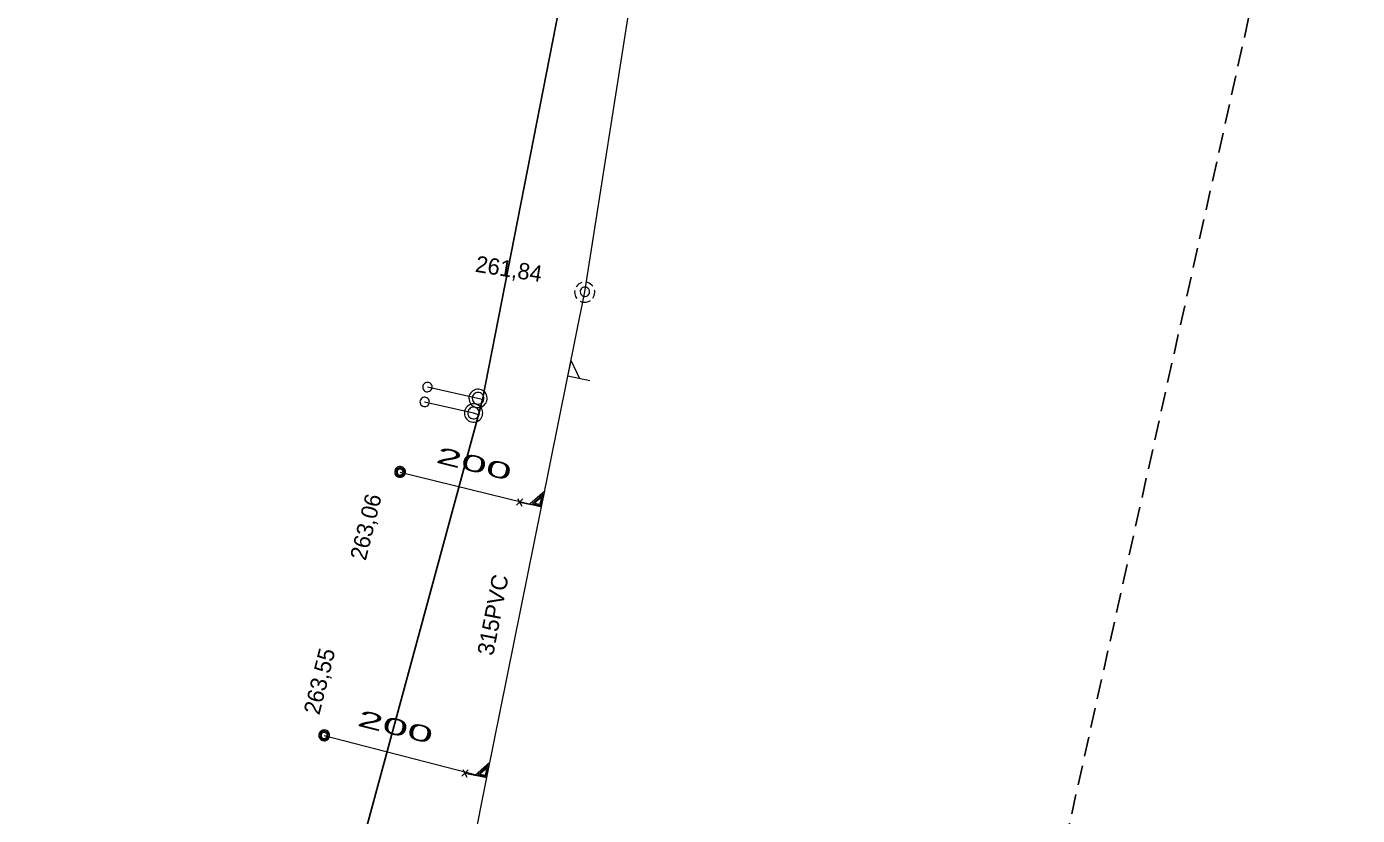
# Model space of a CAD drawing. Extents: x -732096 to -731933, y -1048703 to -1047964.
# Drawn here: x -732033.5 to -731968.4, y -1048192.3 to -1048153.7 of the extents above; entities that cross this region are included whole.
import ezdxf

# ---------------------------------------------------------------- set-up
doc = ezdxf.new("R2010")
doc.units = 0
doc.header["$LTSCALE"] = 0.32
doc.linetypes.add('MEDIUM_DASHED', pattern=[4.5, 3, -1.5])
doc.layers.add('1', color=7, linetype='Continuous')
for name, color, linetype, lineweight in [('18', 7, 'Continuous', 13), ('20', 7, 'Continuous', 13), ('49', 7, 'Continuous', 13), ('63', 7, 'MEDIUM_DASHED', 25), ('8', 7, 'Continuous', 13)]:
    doc.layers.add(name, color=color, linetype=linetype, lineweight=lineweight)

msp = doc.modelspace()

# ---------------------------------------------------------------- linework, layer by layer
at = {"layer": '18'}
for p, q in [((-732009.504, -1048177.097), (-732009.191, -1048176.781)), ((-732009.45, -1048176.762), (-732009.252, -1048177.143)), ((-732012.18, -1048190.343), (-732011.867, -1048190.027)), ((-732012.126, -1048190.008), (-732011.928, -1048190.389))]:
    msp.add_line(p, q, dxfattribs=at)
for points in [[(-732006.313, -1048166.207), (-732006.384, -1048166.235), (-732006.451, -1048166.274), (-732006.511, -1048166.322), (-732006.562, -1048166.379), (-732006.586, -1048166.413)], [(-732005.772, -1048166.39), (-732005.822, -1048166.332), (-732005.88, -1048166.282), (-732005.945, -1048166.241), (-732006.016, -1048166.212), (-732006.065, -1048166.198)], [(-732006.658, -1048166.599), (-732006.664, -1048166.676), (-732006.659, -1048166.753), (-732006.642, -1048166.828), (-732006.613, -1048166.899), (-732006.573, -1048166.965), (-732006.557, -1048166.987)], [(-732005.777, -1048166.976), (-732005.736, -1048166.911), (-732005.705, -1048166.841), (-732005.686, -1048166.766), (-732005.678, -1048166.69), (-732005.683, -1048166.613), (-732005.689, -1048166.578)], [(-732006.4, -1048167.116), (-732006.33, -1048167.147), (-732006.255, -1048167.166), (-732006.179, -1048167.173), (-732006.102, -1048167.168), (-732006.027, -1048167.151), (-732005.955, -1048167.123), (-732005.895, -1048167.088)], [(-732005.918, -1048171.009), (-732006.993, -1048170.792), (-732006.84, -1048170.033), (-732006.428, -1048170.905)], [(-732009.355, -1048176.945), (-732008.281, -1048177.162), (-732008.128, -1048176.406), (-732008.847, -1048177.048)], [(-732008.722, -1048177.021), (-732008.314, -1048177.103), (-732008.202, -1048176.55), (-732008.723, -1048177.021)], [(-732008.63, -1048176.992), (-732008.345, -1048177.049), (-732008.271, -1048176.686), (-732008.63, -1048176.994)], [(-732012.031, -1048190.191), (-732010.957, -1048190.408), (-732010.804, -1048189.652), (-732011.523, -1048190.294)], [(-732011.398, -1048190.267), (-732010.99, -1048190.349), (-732010.878, -1048189.796), (-732011.399, -1048190.267)], [(-732011.306, -1048190.238), (-732011.021, -1048190.295), (-732010.947, -1048189.932), (-732011.306, -1048190.24)]]:
    msp.add_lwpolyline(points, dxfattribs=at)
for points in [[(-732005.929, -1048166.659), (-732005.935, -1048166.607), (-732005.953, -1048166.557), (-732005.981, -1048166.513), (-732006.019, -1048166.476), (-732006.064, -1048166.449), (-732006.114, -1048166.433), (-732006.166, -1048166.428), (-732006.218, -1048166.435), (-732006.267, -1048166.454), (-732006.311, -1048166.484), (-732006.346, -1048166.523), (-732006.372, -1048166.568), (-732006.387, -1048166.619), (-732006.39, -1048166.671), (-732006.382, -1048166.723), (-732006.361, -1048166.771), (-732006.331, -1048166.814), (-732006.291, -1048166.849), (-732006.245, -1048166.873), (-732006.194, -1048166.887), (-732006.142, -1048166.889), (-732006.09, -1048166.879), (-732006.042, -1048166.857), (-732006, -1048166.825), (-732005.967, -1048166.785), (-732005.943, -1048166.738), (-732005.931, -1048166.687)], [(-732014.935, -1048175.467), (-732014.941, -1048175.411), (-732014.958, -1048175.358), (-732014.987, -1048175.309), (-732015.025, -1048175.268), (-732015.071, -1048175.236), (-732015.123, -1048175.214), (-732015.178, -1048175.203), (-732015.234, -1048175.205), (-732015.289, -1048175.218), (-732015.34, -1048175.243), (-732015.384, -1048175.278), (-732015.42, -1048175.321), (-732015.445, -1048175.371), (-732015.46, -1048175.426), (-732015.463, -1048175.482), (-732015.454, -1048175.537), (-732015.433, -1048175.59), (-732015.402, -1048175.636), (-732015.362, -1048175.675), (-732015.314, -1048175.705), (-732015.261, -1048175.724), (-732015.205, -1048175.731), (-732015.149, -1048175.727), (-732015.095, -1048175.71), (-732015.046, -1048175.683), (-732015.004, -1048175.645), (-732014.971, -1048175.6), (-732014.948, -1048175.549), (-732014.936, -1048175.494)], [(-732014.994, -1048175.47), (-732015, -1048175.421), (-732015.018, -1048175.375), (-732015.046, -1048175.334), (-732015.083, -1048175.301), (-732015.127, -1048175.279), (-732015.175, -1048175.267), (-732015.224, -1048175.267), (-732015.272, -1048175.279), (-732015.316, -1048175.302), (-732015.353, -1048175.335), (-732015.381, -1048175.376), (-732015.398, -1048175.423), (-732015.404, -1048175.472), (-732015.397, -1048175.521), (-732015.379, -1048175.567), (-732015.351, -1048175.607), (-732015.314, -1048175.64), (-732015.27, -1048175.662), (-732015.221, -1048175.674), (-732015.172, -1048175.673), (-732015.124, -1048175.661), (-732015.081, -1048175.637), (-732015.044, -1048175.604), (-732015.016, -1048175.563), (-732015, -1048175.516)], [(-732015.053, -1048175.474), (-732015.059, -1048175.432), (-732015.076, -1048175.394), (-732015.104, -1048175.363), (-732015.139, -1048175.34), (-732015.179, -1048175.329), (-732015.221, -1048175.329), (-732015.261, -1048175.341), (-732015.296, -1048175.364), (-732015.323, -1048175.396), (-732015.34, -1048175.434), (-732015.345, -1048175.475), (-732015.339, -1048175.517), (-732015.321, -1048175.554), (-732015.293, -1048175.586), (-732015.257, -1048175.608), (-732015.217, -1048175.619), (-732015.175, -1048175.618), (-732015.135, -1048175.605), (-732015.101, -1048175.582), (-732015.074, -1048175.549), (-732015.058, -1048175.511)], [(-732018.646, -1048188.347), (-732018.652, -1048188.291), (-732018.669, -1048188.238), (-732018.698, -1048188.189), (-732018.736, -1048188.148), (-732018.782, -1048188.116), (-732018.834, -1048188.094), (-732018.889, -1048188.083), (-732018.945, -1048188.085), (-732019, -1048188.098), (-732019.051, -1048188.123), (-732019.095, -1048188.158), (-732019.131, -1048188.201), (-732019.156, -1048188.251), (-732019.171, -1048188.306), (-732019.174, -1048188.362), (-732019.165, -1048188.417), (-732019.144, -1048188.47), (-732019.113, -1048188.516), (-732019.073, -1048188.555), (-732019.025, -1048188.585), (-732018.972, -1048188.604), (-732018.916, -1048188.611), (-732018.86, -1048188.607), (-732018.806, -1048188.59), (-732018.757, -1048188.563), (-732018.715, -1048188.525), (-732018.682, -1048188.48), (-732018.659, -1048188.429), (-732018.647, -1048188.374)], [(-732018.705, -1048188.35), (-732018.711, -1048188.301), (-732018.729, -1048188.255), (-732018.757, -1048188.214), (-732018.794, -1048188.181), (-732018.838, -1048188.159), (-732018.886, -1048188.147), (-732018.935, -1048188.147), (-732018.983, -1048188.159), (-732019.027, -1048188.182), (-732019.064, -1048188.215), (-732019.092, -1048188.256), (-732019.109, -1048188.303), (-732019.115, -1048188.352), (-732019.108, -1048188.401), (-732019.09, -1048188.447), (-732019.062, -1048188.487), (-732019.025, -1048188.52), (-732018.981, -1048188.542), (-732018.932, -1048188.554), (-732018.883, -1048188.553), (-732018.835, -1048188.541), (-732018.792, -1048188.517), (-732018.755, -1048188.484), (-732018.727, -1048188.443), (-732018.711, -1048188.396)], [(-732018.764, -1048188.354), (-732018.77, -1048188.312), (-732018.787, -1048188.274), (-732018.815, -1048188.243), (-732018.85, -1048188.22), (-732018.89, -1048188.209), (-732018.932, -1048188.209), (-732018.972, -1048188.221), (-732019.007, -1048188.244), (-732019.034, -1048188.276), (-732019.051, -1048188.314), (-732019.056, -1048188.355), (-732019.05, -1048188.397), (-732019.032, -1048188.434), (-732019.004, -1048188.466), (-732018.968, -1048188.488), (-732018.928, -1048188.499), (-732018.886, -1048188.498), (-732018.846, -1048188.485), (-732018.812, -1048188.462), (-732018.785, -1048188.429), (-732018.769, -1048188.391)]]:
    msp.add_lwpolyline(points, close=True, dxfattribs=at)
at = {"layer": '20'}
for points in [[(-732006.16, -1048166.67), (-732003.873, -1048152.041), (-732002.097, -1048140.675), (-732000.892, -1048132.965), (-731999.239, -1048122.39)], [(-732006.16, -1048166.67), (-732003.873, -1048152.041), (-732002.097, -1048140.675), (-732000.892, -1048132.965), (-731999.239, -1048122.39)], [(-732011.649, -1048193.85), (-732010.956, -1048190.415), (-732008.28, -1048177.169), (-732006.16, -1048166.67)], [(-732011.649, -1048193.85), (-732010.956, -1048190.415), (-732008.28, -1048177.169), (-732006.16, -1048166.67)]]:
    msp.add_lwpolyline(points, dxfattribs=at)
at = {"layer": '49'}
for p, q in [((-732015.199, -1048175.48), (-732008.28, -1048177.169)), ((-732015.199, -1048175.48), (-732008.28, -1048177.169)), ((-732018.91, -1048188.36), (-732010.956, -1048190.415)), ((-732018.91, -1048188.36), (-732010.956, -1048190.415))]:
    msp.add_line(p, q, dxfattribs=at)
at = {"layer": '63'}
msp.add_lwpolyline([(-731997.077, -1048043.55), (-731968.389, -1048129.387), (-731968.389, -1048129.389), (-731968.389, -1048129.39), (-731968.389, -1048129.392), (-732027.835, -1048396.578)], dxfattribs=at)
at = {"layer": '8'}
for p, q in [((-732011.39, -1048171.88), (-732013.862, -1048171.33)), ((-732011.609, -1048172.6), (-732014, -1048172.057)), ((-732011.172, -1048171.929), (-732011.39, -1048171.88)), ((-732011.368, -1048172.669), (-732011.609, -1048172.6))]:
    msp.add_line(p, q, dxfattribs=at)
at = {"layer": '8', "lineweight": 25}
msp.add_lwpolyline([(-732017.71, -1048097.66), (-732014.489, -1048102.34), (-732013.919, -1048103.111), (-732010.875, -1048108.055), (-732007.12, -1048116.101), (-732004.818, -1048129.764), (-732005.61, -1048138.74), (-732006.8, -1048149.62), (-732011.172, -1048171.929), (-732011.368, -1048172.669), (-732018.564, -1048199.221), (-732025.78, -1048218.541), (-732027.664, -1048223.962), (-732033.46, -1048240.64)], dxfattribs=at)
at = {"layer": '8'}
for points in [[(-732013.637, -1048171.384), (-732013.628, -1048171.333), (-732013.631, -1048171.28), (-732013.646, -1048171.23), (-732013.672, -1048171.183), (-732013.707, -1048171.145), (-732013.751, -1048171.115), (-732013.799, -1048171.096), (-732013.851, -1048171.088), (-732013.904, -1048171.093), (-732013.954, -1048171.109), (-732013.999, -1048171.137), (-732014.036, -1048171.172), (-732014.065, -1048171.217), (-732014.083, -1048171.266), (-732014.09, -1048171.318), (-732014.083, -1048171.37), (-732014.066, -1048171.42), (-732014.038, -1048171.465), (-732014, -1048171.501), (-732013.955, -1048171.529), (-732013.906, -1048171.545), (-732013.853, -1048171.55), (-732013.801, -1048171.543), (-732013.752, -1048171.524), (-732013.709, -1048171.495), (-732013.673, -1048171.456), (-732013.647, -1048171.411)], [(-732010.957, -1048171.994), (-732010.943, -1048171.922), (-732010.94, -1048171.849), (-732010.949, -1048171.777), (-732010.971, -1048171.707), (-732011.003, -1048171.64), (-732011.045, -1048171.581), (-732011.096, -1048171.53), (-732011.156, -1048171.487), (-732011.221, -1048171.454), (-732011.292, -1048171.432), (-732011.364, -1048171.423), (-732011.438, -1048171.426), (-732011.509, -1048171.439), (-732011.578, -1048171.465), (-732011.641, -1048171.502), (-732011.697, -1048171.548), (-732011.746, -1048171.604), (-732011.785, -1048171.665), (-732011.813, -1048171.733), (-732011.829, -1048171.805), (-732011.833, -1048171.877), (-732011.826, -1048171.95), (-732011.808, -1048172.021), (-732011.777, -1048172.087), (-732011.736, -1048172.148), (-732011.686, -1048172.201), (-732011.628, -1048172.246), (-732011.563, -1048172.281), (-732011.494, -1048172.304), (-732011.421, -1048172.315), (-732011.348, -1048172.315), (-732011.276, -1048172.302), (-732011.207, -1048172.279), (-732011.142, -1048172.244), (-732011.084, -1048172.199), (-732011.035, -1048172.145), (-732010.995, -1048172.084), (-732010.965, -1048172.018)], [(-732013.775, -1048172.112), (-732013.766, -1048172.06), (-732013.769, -1048172.007), (-732013.784, -1048171.957), (-732013.81, -1048171.911), (-732013.845, -1048171.872), (-732013.889, -1048171.843), (-732013.937, -1048171.823), (-732013.989, -1048171.815), (-732014.041, -1048171.82), (-732014.092, -1048171.836), (-732014.137, -1048171.863), (-732014.174, -1048171.899), (-732014.203, -1048171.944), (-732014.221, -1048171.993), (-732014.228, -1048172.045), (-732014.221, -1048172.097), (-732014.204, -1048172.147), (-732014.176, -1048172.192), (-732014.138, -1048172.228), (-732014.093, -1048172.256), (-732014.044, -1048172.272), (-732013.991, -1048172.277), (-732013.939, -1048172.27), (-732013.89, -1048172.251), (-732013.847, -1048172.222), (-732013.811, -1048172.183), (-732013.785, -1048172.138)], [(-732011.112, -1048171.949), (-732011.102, -1048171.892), (-732011.103, -1048171.833), (-732011.116, -1048171.776), (-732011.141, -1048171.723), (-732011.175, -1048171.676), (-732011.219, -1048171.637), (-732011.27, -1048171.608), (-732011.326, -1048171.589), (-732011.384, -1048171.583), (-732011.443, -1048171.589), (-732011.499, -1048171.606), (-732011.549, -1048171.634), (-732011.594, -1048171.672), (-732011.63, -1048171.719), (-732011.656, -1048171.771), (-732011.67, -1048171.828), (-732011.673, -1048171.886), (-732011.663, -1048171.944), (-732011.642, -1048171.998), (-732011.61, -1048172.048), (-732011.569, -1048172.089), (-732011.52, -1048172.122), (-732011.466, -1048172.144), (-732011.409, -1048172.154), (-732011.35, -1048172.154), (-732011.293, -1048172.14), (-732011.24, -1048172.115), (-732011.194, -1048172.081), (-732011.155, -1048172.037), (-732011.126, -1048171.986)], [(-732011.176, -1048172.715), (-732011.162, -1048172.643), (-732011.159, -1048172.57), (-732011.168, -1048172.497), (-732011.19, -1048172.427), (-732011.221, -1048172.361), (-732011.263, -1048172.302), (-732011.315, -1048172.25), (-732011.374, -1048172.207), (-732011.44, -1048172.174), (-732011.51, -1048172.153), (-732011.583, -1048172.143), (-732011.656, -1048172.145), (-732011.727, -1048172.159), (-732011.796, -1048172.185), (-732011.86, -1048172.222), (-732011.916, -1048172.268), (-732011.964, -1048172.323), (-732012.003, -1048172.385), (-732012.031, -1048172.453), (-732012.048, -1048172.524), (-732012.052, -1048172.597), (-732012.046, -1048172.669), (-732012.027, -1048172.741), (-732011.996, -1048172.807), (-732011.955, -1048172.868), (-732011.905, -1048172.921), (-732011.848, -1048172.966), (-732011.783, -1048173), (-732011.713, -1048173.024), (-732011.641, -1048173.035), (-732011.568, -1048173.035), (-732011.495, -1048173.023), (-732011.426, -1048172.999), (-732011.362, -1048172.965), (-732011.304, -1048172.919), (-732011.254, -1048172.866), (-732011.214, -1048172.805), (-732011.184, -1048172.738)], [(-732011.331, -1048172.669), (-732011.321, -1048172.612), (-732011.322, -1048172.553), (-732011.335, -1048172.497), (-732011.36, -1048172.443), (-732011.394, -1048172.396), (-732011.438, -1048172.357), (-732011.489, -1048172.328), (-732011.545, -1048172.309), (-732011.602, -1048172.303), (-732011.661, -1048172.309), (-732011.717, -1048172.326), (-732011.768, -1048172.354), (-732011.812, -1048172.392), (-732011.849, -1048172.438), (-732011.875, -1048172.49), (-732011.889, -1048172.547), (-732011.892, -1048172.606), (-732011.882, -1048172.664), (-732011.861, -1048172.718), (-732011.829, -1048172.768), (-732011.788, -1048172.809), (-732011.74, -1048172.842), (-732011.686, -1048172.864), (-732011.628, -1048172.874), (-732011.57, -1048172.874), (-732011.513, -1048172.86), (-732011.46, -1048172.835), (-732011.413, -1048172.801), (-732011.374, -1048172.757), (-732011.345, -1048172.706)]]:
    msp.add_lwpolyline(points, close=True, dxfattribs=at)

# ---------------------------------------------------------------- texts
at = {"layer": '1'}
for s, rotation, p in [('261,84', 351, (-732011.556, -1048165.678)), ('263,06', 76, (-732016.881, -1048179.839)), ('315PVC', 79, (-732010.649, -1048184.488)), ('263,55', 76, (-732019.15, -1048187.384))]:
    msp.add_text(s, height=0.8, rotation=rotation, dxfattribs=at).set_placement(p)
at = {"layer": '1', "width": 2.1}
for p in [(-732013.494, -1048174.997), (-732017.341, -1048187.863)]:
    msp.add_text('200 ', height=0.8, rotation=346, dxfattribs=at).set_placement(p)

doc.saveas('drawing.dxf')
